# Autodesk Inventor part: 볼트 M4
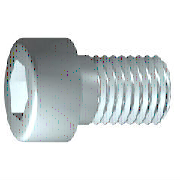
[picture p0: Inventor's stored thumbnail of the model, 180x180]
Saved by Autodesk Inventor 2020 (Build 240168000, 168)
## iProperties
IsCustomPart: 0
Created: 2012-02
Part Number: 볼트 M4
Material: 스테인리스강
Description: 6각 소켓 머리 캡 나사
Document SubType Name: Modeling
Standard: ISO 4762
Designer: mduedu
Standard Revision: Fourth edition 2004-03-01
Standards Organization: ISO
Language: ko-KR
Size Designation: M4 x 12
Categories: <MemberInstance><Categories><Category DisplayName="조임쇠" InternalName="e4da775c-781d-43d5-af7c-5136215cf5a6" Mnemonic="FSTN"><Category DisplayName="볼트" InternalN
Density: 8.08 g/cm^3
Mass: 2.29719 g
Surface Area: 3.30853 cm^2
Volume: 0.284306 cm^3
Appearance: 반광택
Author: mduedu
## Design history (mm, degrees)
sketch "스케치1"
  geometry: L1 (-1, 0)-(12, 0); L2 (12, 0)-(12, 2); L3 (12, 2)-(1.75, 2); L4 (1.75, 2)-(1.32, 2); L5 (1.32, 2)-(0, 2); L6 (0, 2)-(0, 3.5); L7 (0, 3.5)-(-4, 3.5); L8 (-4, 3.5)-(-4, 1.732); L9 (-4, 1.732)-(-2, 1.732); L10 (-2, 1.732)-(-1, 0); L11 (-7.2, 0)-(15.2, 0) reference; L12 (0, -0.7)-(0, 4.2) reference; L13 (1.75, 2)-(0, 2)
  constraints: 22 end point, 6 parallel, 2 collinear, 2 perpendicular, 1 horizontal, 1 point on line
  dimensions: "d1" = 10.25 distance from line of L3.end L2 (= GEL); "d2" = 0.42952 distance of L4.end L3.end (computed from GAL); "d3" = 4 distance between parallel lines of L8 L6 (= KOH); "d4" = 2 distance of L8.end L9.end (= INTI); "d5" = 60 deg angle of L10 L1; "d6" = 4 diameter of L3 L1 (= GD); "d7" = 4 diameter of L5 L1 (= BDM); "d8" = 3.4641 diameter of L9 L1 (= 1.1547 x SW); "d9" = 7 diameter of L7 L1 (= KOD); "d26" = 12 distance between parallel lines of L12 L2 (= NLG)
revolve "본체" sketch "스케치1" stored, may be unused: angle "d10" = 90 deg
sketch "스케치2"
  geometry: L1 (0, -4.9)-(0, 4.9) reference; L2 (-4.9, 0)-(4.9, 0) reference; L3 (1.732, 0)-(0.866, -1.5); L4 (0.866, -1.5)-(-0.866, -1.5); L5 (-0.866, -1.5)-(-1.732, 0); L6 (-1.732, 0)-(-0.866, 1.5); L7 (-0.866, 1.5)-(0.866, 1.5); L8 (0.866, 1.5)-(1.732, 0); 2 further points
  constraints: 12 end point, 1 coincident, 1 horizontal alignment, 1 point on line, 12 other
extrude "슬롯" join sketch "스케치2" stored distance "d11" = 10; taper "d12" = 0 deg
workplane "Work Plane1"
fillet "Fillet2" dims "d30" = 0.1 (= R)
body "Solid1"
fillet "모깎기1" dims "d17" = 0.4 (= RR)
feature "스레드" dims "d13" = 10.25 (= GEL), "d14" = 0
chamfer "모따기1" distance "d15" = 0.42941 (= -0.5 x SPD + 0.5 x GD); stored, may be unused: second distance "d16" = 0.42941 (= GUL), angle "d27" = 45 deg
other parameters: "GD" = 4 [user parameter; used in 2 equation terms], "NLG" = 12 [user parameter; used in 1 equation term], "GEL" = 10.25 [user parameter; used in 2 equation terms], "KOD" = 7 [user parameter; used in 1 equation term], "KOH" = 4 [user parameter; used in 1 equation term], "INTI" = 2 [user parameter; used in 1 equation term], "GAL" = 0.42941 (= 0.61345 x PTC) [user parameter; used in 1 equation term], "GUL" = 0.42941 (= 0.61345 x PTC) [user parameter; used in 1 equation term], "BDM" = 4 (= NND) [user parameter; used in 1 equation term], "SW" = 3 [user parameter; used in 2 equation terms], "RR" = 0.4 [user parameter; used in 1 equation term], "SPD" = 3.14117 (= NND - 1.2269 x PTC) [user parameter; used in 1 equation term], "d19" = 0, "d28" = 0, "d29" = 0, "R" = 0.1 [user parameter; used in 1 equation term], "TOA" = 30 deg [user parameter], "GD1" = 3.14117 (= THREADDIA - 1.2269 x PTC) [user parameter], "THREADDIA" = 4 [user parameter; used in 1 equation term], "FAWI" = 45 deg [user parameter], "TPU" = 14.28571 (computed from PTC) [user parameter], "PTC" = 0.7 [user parameter; used in 5 equation terms], "NND" = 4 [user parameter; used in 2 equation terms], "E0" = 3.465 (= 1.155 x SW) [user parameter]
